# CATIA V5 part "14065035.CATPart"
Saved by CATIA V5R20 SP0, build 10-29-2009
Part number: 14065035
Definition: NONE
Nomenclature: 14065035
Source: Unknown
Description: 14065035
Bounding box of the stored display mesh (mm): x -17.5 to 70, y -46.5 to 36.6, z -36.6 to 36.6
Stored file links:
  C:\Users\Utente\Desktop\IO LAVORO\3D X SITO CF\X SITO\PLASTICA\RF2\14065035.CATPart
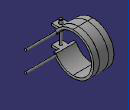
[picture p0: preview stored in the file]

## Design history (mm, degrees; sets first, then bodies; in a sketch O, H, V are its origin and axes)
Body1 "14065035" (main body)
  Solid1: solid without history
